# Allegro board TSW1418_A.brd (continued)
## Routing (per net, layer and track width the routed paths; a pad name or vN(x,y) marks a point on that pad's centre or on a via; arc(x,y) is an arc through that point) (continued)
HA22_N: length 53.2
  TOP w0.152: U9.G4 v1(42.44,40.12)
  LY3-SIGNAL w0.127: v2(6.48,33.48) 6.95,33.95 18.22,33.95 19.13,34.85 19.64,34.85 20.05,34.43 20.05,33.66 20.37,33.34 20.83,33.34 21.15,33.66 21.15,34.43 21.27,34.56 21.45,34.56 21.58,34.43 21.58,33.66 21.9,33.34 22.35,33.34 22.67,33.66 22.67,34.43 22.8,34.56 22.98,34.56 23.1,34.43 23.1,33.66 23.42,33.34 23.87,33.34 24.19,33.66 24.19,34.43 24.32,34.56 24.5,34.56 24.63,34.43 24.63,34.27 24.95,33.95 26.44,33.95 27.2,34.71 27.2,35.43 27.33,35.56 27.86,35.56 28.18,35.88 28.18,36.63 28.31,36.75 28.49,36.75 28.62,36.63 28.62,34.69 28.94,34.37 29.39,34.37 29.71,34.69 29.71,36.63 29.83,36.75 30.01,36.75 30.14,36.63 30.14,35.88 30.46,35.56 31.05,35.56 31.81,36.32 38.86,36.32 39.82,37.28 40.99,37.28 41.78,38.07 42.04,38.33 42.04,39.5 42.44,39.9 v1(42.44,40.12)
HA22_P: length 53.2
  TOP w0.152: U9.G3 v1(41.64,40.12)
  LY3-SIGNAL w0.127: v1(41.64,40.12) 41.64,39.87 41.28,39.5 41.28,38.09 40.8,37.61 39.69,37.61 38.73,36.65 37.77,36.65 37.6,36.83 37.34,36.83 37.16,36.65 36.91,36.65 36.73,36.83 36.48,36.83 36.3,36.65 36.05,36.65 35.87,36.83 35.62,36.83 35.44,36.65 35.18,36.65 35.01,36.83 34.75,36.83 34.57,36.65 33.63,36.65 33.42,36.87 33.24,36.87 33.02,36.65 31.67,36.65 30.91,35.89 30.6,35.89 30.47,36.02 30.47,36.76 30.15,37.08 29.7,37.08 29.38,36.76 29.38,34.82 29.25,34.7 29.07,34.7 28.95,34.82 28.95,36.76 28.63,37.08 28.17,37.08 27.85,36.76 27.85,36.02 27.73,35.89 27.19,35.89 26.87,35.57 26.87,34.85 26.3,34.28 25.08,34.28 24.96,34.4 24.96,34.57 24.64,34.89 24.18,34.89 23.86,34.57 23.86,33.79 23.74,33.67 23.56,33.67 23.43,33.79 23.43,34.57 23.11,34.89 22.66,34.89 22.34,34.57 22.34,33.79 22.21,33.67 22.04,33.67 21.91,33.79 21.91,34.57 21.59,34.89 21.14,34.89 20.82,34.57 20.82,33.79 20.69,33.67 20.51,33.67 20.38,33.79 20.38,34.57 19.77,35.18 18.99,35.18 18.09,34.28 6.95,34.28 v2(6.48,34.75)
HA23_N: length 53.2
  TOP w0.152: U9.G6 v1(44.04,40.12)
  LY3-SIGNAL w0.127: v2(5.21,32.21) 5.68,32.68 29.02,32.68 29.49,33.15 30.74,33.15 31.25,33.65 31.25,33.91 31.38,34.04 31.56,34.04 31.68,33.91 31.68,33.09 32,32.77 32.45,32.77 32.77,33.09 32.77,33.91 32.9,34.04 33.08,34.04 33.21,33.91 33.21,33.09 33.53,32.77 33.98,32.77 34.3,33.09 34.3,33.91 34.42,34.04 34.6,34.04 34.73,33.91 34.73,33.09 35.05,32.77 35.5,32.77 35.82,33.09 35.82,33.91 35.95,34.04 36.13,34.04 36.25,33.91 36.25,33.09 36.57,32.77 37.03,32.77 37.35,33.09 37.35,33.63 37.47,33.76 39.56,33.76 41.54,35.74 43.06,35.74 43.55,36.23 43.55,37.27 43.55,38.65 43.86,38.95 44.19,38.95 44.41,39.17 44.41,39.75 v1(44.04,40.12)
HA23_P: length 53.2
  TOP w0.152: U9.F6 v1(44.04,40.92)
  LY3-SIGNAL w0.127: v1(44.04,40.92) 43.61,40.48 43.61,39.17 43.22,38.78 43.22,38.37 43.08,38.22 43.08,37.94 43.22,37.79 43.22,37.16 43.22,36.37 42.93,36.07 41.4,36.07 39.42,34.09 37.34,34.09 37.02,33.77 37.02,33.22 36.89,33.1 36.71,33.1 36.58,33.22 36.58,34.05 36.26,34.37 35.81,34.37 35.49,34.05 35.49,33.22 35.37,33.1 35.19,33.1 35.06,33.22 35.06,34.05 34.74,34.37 34.29,34.37 33.97,34.05 33.97,33.22 33.84,33.1 33.66,33.1 33.54,33.22 33.54,34.05 33.22,34.37 32.76,34.37 32.44,34.05 32.44,33.22 32.32,33.1 32.14,33.1 32.01,33.22 32.01,34.05 31.69,34.37 31.24,34.37 30.92,34.05 30.92,33.79 30.61,33.48 29.35,33.48 28.88,33.01 5.68,33.01 v2(5.21,33.48)
INIT_B_0: length 78.4
  TOP w0.127: R21.2 v1(44.96,28.19)
  TOP w0.152: U9.P7 v1(44.84,33.72) ; v1(107.82,26.16) 107.82,22.1 107.52,21.79 U20.2
  LY3-SIGNAL w0.127: v1(44.96,28.19) 44.96,27.18 45.59,26.54 45.59,25.53 45.85,25.27 49.52,25.27 49.63,25.38 49.94,25.38 50.05,25.27 52.86,25.27 53.36,25.77 90.34,25.77 90.34,25.83 90.55,26.05 90.86,26.05 91.07,25.83 91.07,25.77 91.19,25.77 91.58,26.16 v1(107.82,26.16)
  LY5-SIGNAL w0.127: v1(44.96,28.19) 44.96,28.7 45.34,29.08 45.34,32.38 44.84,32.88 v1(44.84,33.72)
JTAG_BS_EN: length 9.9
  TOP w0.152: U7.15 91.38,29.72 R19.1 84.71,29.72 R92.2
JTAG_SEL: length 49.7
  TOP w0.127: U20.5 v1(109.65,20.49) ; v1(95.77,29.09) U7.1 98.8,29.09 R18.1
  LY5-SIGNAL w0.127: v1(95.77,29.09) 95.77,29.07 97.41,27.43 102.74,27.43 106.68,23.5 106.68,23.46 v1(109.65,20.49)
  BOTTOM w0.254: v1(109.65,20.49) 103.63,14.48 88.65,14.48 87.5,13.34 TP9.1
LED0: length 43
  TOP w0.152: R88.2 68.81,24.92 66.88,22.99 v1(66.8,22.99) U18.1 ; U9.B12 v1(49.64,44.12)
  BOTTOM w0.152: v1(49.64,44.12) 50.98,44.12 51.44,44.58 53.06,44.58 53.09,44.55 53.4,44.55 53.43,44.58 59.05,44.58 60.5,43.13 60.5,42.16 60.45,42.11 60.45,38.79 69.15,30.09 69.15,24.07 68.07,22.99 v1(66.8,22.99)
LED1: length 44
  TOP w0.127: U18.3 v1(67.31,20.45) ; 67.94,26.15 v1(67.94,24.89)
  TOP w0.152: U9.B11 48.55,43.72 v1(48.9,44.07) ; R87.2 67.03,27.06 67.94,26.15
  LY3-SIGNAL w0.127: v1(67.94,24.89) 67.94,22.48 67.31,21.84 v1(67.31,20.45)
  BOTTOM w0.152: v1(67.94,24.89) 67.94,26.67 60.33,34.29 60.33,38.48 59.69,39.12 59.69,41.78 60.2,42.29 60.2,42.93 59.44,43.69 52.7,43.69 52.32,43.31 52.07,43.31 51.68,43.7 51.09,43.7 51.08,43.69 49.28,43.69 v1(48.9,44.07)
LED2: length 48
  TOP w0.127: U18.5 v1(67.18,17.91) ; R89.2 61.25,31.72 62.78,30.19 62.78,26.84 65.05,24.56 66.98,24.56 v1(67.18,24.77) ; U9.F15 v1(52.04,40.92)
  LY3-SIGNAL w0.127: v1(67.18,24.77) 67.18,22.11 66.94,21.87 66.94,20.3 67.18,20.06 v1(67.18,17.91)
  BOTTOM w0.152: v1(52.04,40.92) 53.11,40.92 53.53,40.5 53.8,40.5 53.91,40.39 54.36,40.39 54.48,40.26 56.01,40.26 56.87,39.4 56.87,36.88 57.78,35.97 57.78,33.43 57.94,33.27 60.2,33.27 63.88,29.59 63.88,26.29 65.15,25.02 66.93,25.02 v1(67.18,24.77)
LED3: length 46.8
  TOP w0.127: U18.9 67.82,16.64 67.18,16 55.5,16 54.61,16.89 v1(54.61,20.65) ; U9.H14 v1(51.24,39.32)
  LY5-SIGNAL w0.127: v1(51.24,39.32) 51.13,39.32 50.7,38.88 50.29,38.88 50.04,38.63 50.04,37.97 50.55,37.47 55.5,37.47 56.52,36.45 56.52,32.51 57.28,31.75 57.28,28.71 57.17,28.6 57.17,28.3 57.28,28.19 57.28,23.24 54.69,20.65 v1(54.61,20.65)
MISO: length 75.6
  TOP w0.127: U9.J14 v1(51.24,38.52)
  TOP w0.152: U7.6 v1(95.72,32.34)
  LY5-SIGNAL w0.127: 94.87,31.5 94.49,31.88 89.55,31.88 88.42,30.75 77.46,30.75 74.8,33.4 71.37,33.4 69.47,35.31 63.63,35.31 60.7,38.24 55.38,38.24 55.17,38.02 52.02,38.02 51.52,38.52 v1(51.24,38.52)
  LY5-SIGNAL w0.152: v1(95.72,32.34) 94.87,31.5 94.87,27.18 95.89,26.16 101.73,26.16 102.23,25.65 J11.3
MOSI: length 60.6
  TOP w0.127: U7.10 v1(93.7,32.99) ; v1(103.25,32) U10.2
  TOP w0.152: U9.G17 v1(53.64,40.12)
  LY3-SIGNAL w0.127: v1(93.7,32.99) 96.55,32.99 98.17,31.37 99.31,31.37 100.46,32.51 102.74,32.51 v1(103.25,32)
  LY5-SIGNAL w0.127: v1(93.7,32.99) 93.42,33.27 89.66,33.27 87.69,31.31 79.82,31.31 76.71,34.42 74.42,34.42 71.88,36.96 66.04,36.96 65.53,37.47 62.87,37.47 60.21,40.12 v1(53.64,40.12)
MOSI_Z: length 31.8
  TOP w0.152: U10.4 v1(108.16,29.8)
  LY5-SIGNAL w0.152: v1(108.16,29.8) 108.58,29.37 108.58,25.53 108.2,25.15 108.2,23.37 110.49,21.08 110.49,11.96 110.34,11.81 100.97,11.81 J11.5
OSC-OUT: length 23.8
  TOP w0.152: R38.2 v1(64.64,48.13) ; U9.H16 v1(52.84,39.32)
  LY3-SIGNAL w0.127: v1(64.64,48.13) 54.36,48.13 50.04,43.81 50.04,42.67 50.42,42.29 50.43,42.29 50.81,41.91 50.81,40.84 52.3,39.34 52.82,39.34 v1(52.84,39.32)
PROGRAM_B_0: length 70
  TOP w0.127: v1(106.63,28.91) R86.2 U20.1 ; U9.P9 v1(46.44,33.72)
  LY3-SIGNAL w0.127: v1(46.44,33.72) 46.93,33.72 47.37,33.27 49.48,33.27 49.49,33.28 61.8,33.28 62.57,32.51 67.44,32.51 71.37,28.57 86.36,28.57 87.25,29.46 97.03,29.46 97.54,28.96 105.66,28.96 105.71,28.91 v1(106.63,28.91)
SCL: length 175
  TOP w0.127: U14.5 133.46,11.13 132.92,11.67 131.46,11.67 ; 121.17,13.46 121.17,13.57 121.03,13.72 120.65,13.72 120.14,14.22 112.65,14.22 112.39,14.48 112.39,21.14 U20.6 ; 121.17,13.46 U17.1 ; 121.17,13.46 v1(121.67,13.96) U17.2 ; U16.5 133.46,36.72 133.1,37.08 131.7,37.08 131.46,36.85 ; U9.F18 v1(63.04,40.52) ; 131.46,11.67 130.86,12.27 U17.5 v1(123.17,13.95) ; 131.46,11.67 U14.1 ; 123.17,37.35 122.68,37.85 121.41,37.85 121.17,37.61 U12.1 ; 123.17,37.35 U12.5 123.17,34.69 123.44,34.42 123.95,34.42 v1(124.21,34.67) ; 123.17,37.35 130.95,37.35 131.46,36.85 ; 131.46,36.85 U16.1 ; U4.44 v1(95.98,36.1)
  TOP w0.152: R97.2 121.15,35.66 U12.1
  LY5-SIGNAL w0.127: v1(124.21,34.67) 124.21,33.27 123.44,32.51 123.44,24.89 124.33,24 124.33,20.57 126.05,18.86 126.05,14.41 125.73,14.1 123.32,14.1 v1(123.17,13.95) 123.17,13.96 v1(121.67,13.96) 116.71,18.92 113.67,18.92 112.39,20.19 112.39,28.07 108.33,32.13 108.33,34.54 106.05,36.83 96.65,36.83 95.98,36.17 v1(95.98,36.1) 95.4,35.51 78.61,35.51 74.88,39.24 73.03,39.24 72.26,38.48 70.25,38.48 69.61,39.12 63.75,39.12 63.04,39.83 v1(63.04,40.52)
SCLK: length 76.4
  TOP w0.127: v1(50.44,38.52) U9.J13
  TOP w0.152: U7.13 v1(92.78,31.04)
  LY5-SIGNAL w0.127: v1(92.78,31.04) 92.58,31.24 89.31,31.24 86.83,28.77 77.91,28.77 74.17,32.51 70.87,32.51 68.58,34.8 63.63,34.8 60.47,37.96 55.86,37.96 55.65,37.74 51.03,37.74 50.44,38.33 v1(50.44,38.52)
  LY5-SIGNAL w0.152: v1(92.78,31.04) 90.82,29.08 89.79,29.08 88.01,27.3 88.01,18.16 93.09,13.08 J11.7
SDA: length 140.1
  TOP w0.127: 122.49,14.41 122.68,14.22 122.68,12.28 U17.4 122.67,10.3 124.59,8.38 132.46,8.38 132.96,8.88 U14.4 ; v1(113.34,21.79) U20.7 ; R85.1 97.03,36.32 v1(96.98,36.37) U4.46 ; v1(122.56,37.08) 122.67,36.97 U12.4 ; v1(108.12,36.37) 108.12,35.54 U8.4 ; U16.4 132.84,35.51 132.84,36.42 132.69,36.58 v1(132.11,36.58) 131.96,36.42 U16.2 ; U9.G18 54.2,39.72 54.48,40 55.71,40 55.99,39.72 v1(62.61,39.72)
  TOP w0.152: v1(113.34,21.79) 113.34,15.06 113.67,14.73 122.17,14.73 122.49,14.41
  LY3-SIGNAL w0.127: v1(96.98,36.37) 97.27,36.08 107.84,36.08 v1(108.12,36.37)
  LY5-SIGNAL w0.127: v1(122.56,37.08) 122.75,36.89 ; 122.75,36.89 123.06,36.58 v1(132.11,36.58) ; 122.75,36.89 122.22,36.37 114.2,36.37 113.34,35.5 113.34,34.9 113.18,34.75 ; v1(96.98,36.37) 95.42,34.8 78.61,34.8 74.8,38.61 73.66,38.61 73.03,37.97 70.36,37.97 69.85,38.48 62.99,38.48 62.61,38.86 v1(62.61,39.72) ; 113.18,34.75 113.06,34.62 110.31,34.62 108.57,36.37 v1(108.12,36.37) ; 113.18,34.75 113.18,21.95 v1(113.34,21.79)
SDA_OUT: length 13.8
  TOP w0.152: U4.45 v1(96.48,39.33) ; v1(105.46,38.69) U8.1 105.39,37.47 R96.2
  LY5-SIGNAL w0.127: v1(96.48,39.33) 97.13,38.69 v1(105.46,38.69)
SEN: length 77
  TOP w0.152: U9.H17 v1(53.64,39.32) ; U7.3 v1(95.8,30.39)
  LY5-SIGNAL w0.127: v1(95.8,30.39) 96.9,31.5 96.9,32.26 96.45,32.71 95.57,32.71 95.37,32.51 93.48,32.51 93.28,32.71 89.99,32.71 88.3,31.03 78.45,31.03 75.56,33.91 72.52,33.91 70.48,35.94 63.75,35.94 60.07,39.62 57.66,39.62 57.29,39.26 55.4,39.26 55.34,39.32 v1(53.64,39.32)
  LY5-SIGNAL w0.152: J11.1 104.78,24.38 102.23,26.92 96.52,26.92 95.25,28.19 95.25,29.82 95.8,30.37 v1(95.8,30.39)
SOUT0: length 3.4
  BOTTOM w0.279: R45.1 R99.2 C90.1 R46.2
SOUT1: length 3.4
  BOTTOM w0.279: R44.2 C89.1 R98.2 R43.1
SPI_D_Z: length 59.5
  TOP w0.127: U10.1 105.39,33.02 v1(103.38,33.02) ; U4.43 95.48,36.56 v1(95.25,36.32)
  TOP w0.152: U9.J15 51.67,38.12 52.05,37.74 54.2,37.74 54.21,37.74 55.24,37.74 55.93,37.06 62.36,37.06 64.59,34.82 77.32,34.82 78.49,35.99 v1(91.67,35.99)
  LY3-SIGNAL w0.127: v1(95.25,36.32) 95.25,35.05 95.76,34.54 101.85,34.54 v1(103.38,33.02)
  BOTTOM w0.152: v1(91.67,35.99) 94.92,35.99 v1(95.25,36.32)
SYNC0: length 4.4
  TOP w0.279: U9.A10 47.75,44.63 v1(47.75,48.9)
SYNC0_VADJ: length 25.8
  TOP w0.254: U9.R3 v1(41.64,32.92)
  LY3-SIGNAL w0.127: v1(48.77,52.2) 49.4,51.56 49.4,48.78 46.88,46.25 46.88,44.81 46.99,44.7 46.99,35.18 46.74,34.92 42.67,34.92 41.64,33.9 v1(41.64,32.92)
SYNC1: length 5
  TOP w0.279: U9.A11 48.44,46.67 50.04,48.26 v1(50.04,48.9)
SYNC1_VADJ: length 25.1
  TOP w0.152: U9.P4 v1(42.44,33.72)
  LY3-SIGNAL w0.127: v1(51.05,52.2) 50.67,51.82 50.67,48.13 48.51,45.97 48.51,45.21 47.5,44.2 47.5,34.54 47.11,34.15 42.92,34.15 42.48,33.72 v1(42.44,33.72)
SYNC-OUT-0: length 19.9
  BOTTOM w0.279: R45.2 47.75,56.39 50.42,59.05 55.88,59.05 58.29,61.47 J8.1
SYNC-OUT-1: length 31.5
  BOTTOM w0.279: J7.1 71.63,59.31 69.47,57.15 52.07,57.15 50.04,55.12 R43.2
TCK: length 63.6
  TOP w0.127: J3.6 92.62,25.18 R79.2 94.11,26.67 94.11,29.59 93.3,30.39 U7.14 v1(89.83,30.39) ; U9.E10 47.64,41.32 v1(48.04,41.72)
  LY3-SIGNAL w0.127: v1(48.04,41.72) 48.07,41.72 48.48,41.31 48.48,38.99 48.53,38.94 49.74,38.94 50.08,38.6 50.08,38.19 50.16,38.1 50.75,38.1 50.81,38.04 50.98,37.87 51.38,37.87 51.66,37.6 51.81,37.6 51.97,37.44 52.05,37.44 52.08,37.41 52.31,37.41 52.56,37.41 52.64,37.34 56.11,37.34 56.23,37.21 61.08,37.21 62.67,35.62 62.67,35.36 63.11,34.92 89.11,34.92 89.26,35.07 89.56,35.07 89.77,34.86 89.77,34.81 90.08,34.5 90.08,30.65 v1(89.83,30.39)
TDI: length 62.8
  TOP w0.127: J3.10 96.61,24.67 94.74,26.54 94.74,30.73 v1(93.13,32.34) U7.11 ; v1(48.84,41.72) 48.44,41.32 U9.E11
  LY3-SIGNAL w0.127: v1(93.13,32.34) 92.94,32.34 92.45,32.84 92.45,33.03 90.04,35.43 63.88,35.43 61.85,37.47 61.53,37.47 61.03,37.97 56.23,37.97 56.01,37.75 52.62,37.75 52.57,37.69 52.19,37.69 52.01,37.87 51.78,37.87 51.5,38.15 51.09,38.15 50.81,38.44 50.81,38.67 50.6,38.88 50.27,38.88 50.04,39.12 50.04,39.44 49.8,39.68 49.47,39.68 49.28,39.88 49.28,41.27 48.84,41.71 v1(48.84,41.72)
TDO: length 75.3
  TOP w0.127: U9.E13 50.04,41.32 v1(50.44,41.72) ; U7.5 97.24,31.88 v1(98.42,31.88) ; J3.8 v1(94.61,25.02) ; v1(101.47,25.02) v1(101.47,31.88)
  LY3-SIGNAL w0.127: v1(98.42,31.88) 98.81,32.26 98.81,33.78 98.42,34.16 93.09,34.16 91.63,35.63 91.52,35.63 91.3,35.84 91.3,35.95 91.26,35.99 64.21,35.99 61.62,38.58 55.98,38.58 55.88,38.48 54.1,38.48 53.7,38.88 52.69,38.88 52.67,38.86 52.26,38.86 51.09,40.03 51.09,40.1 50.44,40.74 v1(50.44,41.72)
  LY5-SIGNAL w0.127: v1(101.47,31.88) v1(98.42,31.88) ; v1(94.61,25.02) v1(101.47,25.02)
TMS: length 77
  TOP w0.127: v1(49.64,41.72) 49.24,41.32 U9.E12 ; U7.2 v1(98.45,29.74) 98.81,30.1 R80.2 ; v1(100.74,29.74) v1(100.74,25.68) ; v1(90.7,25.68) 90.62,25.59 J3.4
  LY3-SIGNAL w0.127: v1(98.45,29.74) 96.95,31.24 95.25,31.24 93.86,32.63 93.85,32.63 93.55,32.63 93.33,32.84 93.33,33.15 93.34,33.15 90.78,35.71 64.1,35.71 61.71,38.1 61.59,38.1 61.42,38.27 56.11,38.27 55.93,38.1 52.66,38.1 52.64,38.07 52.21,38.07 52.13,38.15 51.89,38.15 51.68,38.37 51.68,38.6 51.33,38.95 51.09,38.95 50.88,39.17 50.88,39.4 50.6,39.68 50.35,39.68 50.04,40 50.04,41.33 v1(49.64,41.72)
  LY5-SIGNAL w0.127: v1(98.45,29.74) v1(100.74,29.74) ; v1(100.74,25.68) v1(90.7,25.68)
TRIG: length 6.8
  TOP w0.127: U9.A9 46.84,47.26 46.1,48.01 R39.2
  TOP w0.279: C85.2 R40.1 R39.2
TRIG-IN: length 17.4
  TOP w0.279: J5.1 44.96,60.96 43.81,59.82 C85.1
USB_EECLK: length 8.4
  TOP w0.152: U4.62 101.84,46.18 104.42,48.77 104.65,48.77 R8.2 U5.2
USB_EECS: length 10
  TOP w0.152: U5.1 R7.2 103.63,50.67 103.1,50.14 103.1,47.93 101.85,46.68 U4.63
USB_REF: length 1.8
  TOP w0.152: U4.6 v1(95.48,47.77)
  BOTTOM w0.152: R5.2 95.48,47.26 v1(95.48,47.77)
USB_RST: length 3.7
  TOP w0.381: U4.14 91.48,50.88 C18.1 R4.2
VADJ: length 37.6
  TOP w0.254: U9.D6 44.44,42.12 v1(44.04,42.52) ; U9.V8 46.04,30.68 v1(45.85,30.48) ; U9.N3 v1(41.64,34.52) ; U9.F2 v1(40.84,40.92) ; U9.L15 v1(52.04,36.12) ; v1(43.31,31.37) 43.31,31.38 U9.U5 ; U9.L17 v1(53.64,36.12) ; U9.J1 v1(40.15,38.12) ; U9.G5 v1(43.24,40.12) ; U9.P16 v1(52.84,33.72) ; U9.V18 v1(54.04,30.41) ; U9.P6 v1(44.04,33.72) ; U9.N13 v1(50.44,34.52) ; U9.T2 v1(40.84,32.12) ; U9.C3 v1(41.64,43.32) ; U9.A7 v1(45.24,44.93) ; U9.T12 v1(49.64,32.12) ; U9.K4 v1(42.44,36.92) ; U9.U15 v1(52.04,31.32)
  TOP w0.457: J13.2 116.16,19.48 ; J13.2 116.38,20.19 ; J13.2 114.5,20.19 ; J13.2 116.16,20.91 ; J13.2 115.44,21.13 ; J13.2 115.44,19.25 ; J13.2 114.73,20.91 ; J13.2 114.73,19.48
  TOP w0.508: C127.1 v1(118.62,20.19)
  LYR9-PWR w0.457: J13.2 115.44,21.13 ; J13.2 116.16,19.48 ; J13.2 116.16,20.91 ; J13.2 115.44,19.25 ; J13.2 116.38,20.19 ; J13.2 114.73,20.91 ; J13.2 114.5,20.19 ; J13.2 114.73,19.48
  BOTTOM w0.254: C50.1 41.62,34.54 v1(41.64,34.52) ; C52.1 39.69,38.12 v1(40.15,38.12) ; C57.1 51.92,35.99 v1(52.04,36.12) ; v1(45.85,30.48) 45.85,29.9 C53.1 ; C56.1 52.83,33.71 v1(52.84,33.72) ; C43.1 v1(52.5,30.4) ; v1(40.84,40.92) 40.79,40.92 40.73,40.97 40.26,41.45 39.7,41.45 39.45,41.2 39.45,41.18 C47.1 ; v1(42.44,36.92) 42.36,36.83 C58.1 ; C40.1 v1(42.55,46.1) ; C59.1 v1(55.19,32.82) ; v1(45.24,44.93) 45.24,45.45 C51.1 ; C45.1 v1(43.31,31.37)
  BOTTOM w0.508: C54.1 v1(55.37,29.97) ; C54.1 v1(56.26,30.1) ; C54.1 v1(56.39,30.99)
  vias: v1(39.29,43.15) v1(39.42,39.12) v1(39.55,42.16) v1(42.34,47.62) v2(7.75,10.62) v2(9.02,11.89) v2(10.29,10.62) v2(11.56,11.89)
N24747082: length 2.9
  TOP w0.152: U5.4 105.54,46.86 R10.2 R9.2
N25673570: length 6.9
  TOP w0.254: U4.9 v1(93.98,47.25)
  BOTTOM w0.254: v1(93.98,47.25) 93.98,49.13 C2.1 C1.1 FB1.1
N25674940: length 6.8
  TOP w0.254: v1(96.39,47.37) 96.48,47.46 U4.4
  BOTTOM w0.254: v1(96.39,47.37) 96.62,47.6 C12.1 C14.1 FB2.1
N27319544: length 11
  TOP w0.152: 101.68,53.05 C19.1 ; 101.68,53.05 101.68,52.66 101.17,52.15 100.99,52.15 100.92,52.22 100.73,52.22 100.6,52.08 100.6,51.89 100.66,51.83 100.66,51.64 100.46,51.44 100.07,51.44 99.82,51.18 99.61,51.18 99.49,51.31 99.49,51.56 99.36,51.69 99.16,51.69 99.03,51.56 99.03,51.31 98.9,51.18 98.7,51.18 98.57,51.31 98.57,51.56 98.45,51.69 98.24,51.69 97.99,51.44 97.66,51.44 97.48,51.26 U4.2 ; 101.68,53.05 Y1.1
N27322325: length 11.1
  TOP w0.152: Y1.3 101.66,56.24 C21.1 96.98,53.17 U4.3
N29832220: length 0.8
  TOP w0.254: FB4.1 v1(90.68,60.45)
  vias: v1(88.52,69.98) v1(88.52,67.82) v1(88.52,63.63) v1(88.52,61.59) v1(89.03,67.18) v1(89.03,64.77) v1(89.03,60.96) v1(89.03,59.94) v1(89.66,61.59) v1(89.92,65.91) v1(90.68,67.18) v1(90.68,64.77) v1(91.19,69.72) v1(91.19,67.82) v1(91.31,64.26) v1(91.31,61.72) v1(91.57,63.12) v1(92.96,69.85) v1(92.96,68.2) v1(94.36,69.09) v1(94.36,67.18) v1(94.36,65.15) v1(95.76,69.85) v1(95.76,68.2) v1(97.41,69.72) v1(97.41,67.82) v1(97.41,64.01) v1(97.41,62.1) v1(98.04,64.64) v1(98.17,67.18) v1(98.68,65.79) v1(99.31,67.18) v1(99.44,64.64) v1(99.95,61.59) v1(100.08,69.98) v1(100.08,66.04)
N46253696: length 3.7
  TOP w0.152: J2.1 95.94,60.65 C16.1 FB3.1
N46253708: length 12.5
  TOP w0.152: R3.1 FB3.2 98.3,58.17 102.11,61.98 102.11,63.25 TP7.1
N46266315: length 1.7
  TOP w0.254: C15.1 111.72,40.2 U2.4
N46266800: length 3.4
  TOP w0.254: U4.59 101.71,44.68 101.98,44.96 101.98,43.81
N46270507: length 7.2
  TOP w0.152: U9.P11 v1(48.84,33.72) ; v1(48.64,28.32) 49.15,28.07 R22.2
  LY5-SIGNAL w0.127: v1(48.84,33.72) 48.77,33.64 48.77,31.85 48.48,31.56 48.48,29.56 48.39,29.46 48.39,28.57 v1(48.64,28.32)
N46270525: length 7
  TOP w0.152: v1(51.44,28.45) R23.2 ; U9.P13 v1(50.44,33.72)
  LY5-SIGNAL w0.127: v1(51.44,28.45) 51.44,28.96 51.24,29.15 51.24,29.23 51.03,29.44 51.03,29.63 51.02,29.64 51.02,29.73 50.93,29.82 50.93,31.12 50.88,31.17 50.88,31.47 50.93,31.52 50.93,32.72 50.88,32.77 50.88,33.07 50.44,33.5 v1(50.44,33.72)
N46270552: length 7.8
  TOP w0.152: v1(50.55,28.32) 50.29,28.07 R24.2 ; U9.P12 v1(49.64,33.72)
  LY5-SIGNAL w0.127: v1(49.64,33.72) 49.64,33.41 49.52,33.28 49.49,33.28 49.28,33.07 49.28,32.9 49.28,32.89 49.28,28.96 49.91,28.32 v1(50.55,28.32)
N46270638: length 7.3
  TOP w0.127: R25.2 v1(46.1,28.19)
  TOP w0.152: U9.P8 v1(45.64,33.72)
  LY5-SIGNAL w0.127: v1(46.1,28.19) 46.1,28.7 45.64,29.16 45.64,29.76 46.21,30.33 46.21,30.63 45.64,31.2 v1(45.64,33.72)
N46271778: length 2
  TOP w0.152: R1.2 86.66,40.68 U4.30
N46271783: length 2.1
  TOP w0.254: U4.55 101.97,42.68 101.98,42.67
N46280543: length 3.5
  TOP w0.152: R13.2 67.06,37.95 C23.1 67.46,38.35 U6.2
N46280553: length 3.5
  TOP w0.152: U6.1 67.57,39 C22.1 67.06,39.52 R12.2
N46323629: length 2.2
  TOP w0.152: R33.2 TP11.1
N46323688: length 2.2
  TOP w0.152: R34.2 TP12.1
N46333997: length 3.8
  TOP w0.254: C92.1 R49.2 121.07,51.5 U11.1
N46334199: length 44.6
  TOP w0.127: v1(130.63,25.7) 131.23,25.7 131.36,25.83 U13.1 ; v1(117.6,51.82) R50.1
  LY5-SIGNAL w0.127: v1(130.63,25.7) 130.63,27.26 131.83,28.45 131.83,30.48 133.6,32.26 133.6,35.18 133.35,35.43 133.35,36.96 130.78,39.53 130.78,43.08 128.78,45.09 128.78,50.67 127.51,51.94 117.73,51.94 v1(117.6,51.82)
  BOTTOM w0.127: R77.2 119.13,50.29 v1(117.6,51.82)
N46334233: length 5.8
  TOP w0.254: U11.7 121.72,55.05 122.43,55.75 122.43,57.18 R52.1 R51.2
N46334693: length 5.3
  TOP w0.254: 122.17,41.4 121.67,40.9 U12.9 ; 122.17,41.4 122.17,41.76 C96.2 122.45,43.64 R54.2 ; 122.17,41.4 U12.8
N46334712: length 3.8
  TOP w0.254: R53.2 120.9,42.06 C96.1 121.17,41.74 U12.10
N46335690: length 5.9
  TOP w0.254: U13.7 132.01,29.39 132.28,29.67 132.48,29.67 132.64,29.83 132.64,30.02 132.72,30.1 132.72,31.14 R64.2 R58.1
N46335801: length 5.4
  TOP w0.254: U14.9 131.96,14.99 132.46,15.49 ; 132.46,15.49 132.46,15.72 C103.2 132.72,16.03 R60.2 ; 132.46,15.49 U14.8
N46335828: length 3.8
  TOP w0.254: U14.10 131.46,15.71 C103.1 131.17,17.6 R59.2
N46336358: length 1.9
  TOP w0.254: R62.1 131.72,50.44 131.95,50.67 131.95,51.43 132.01,51.48 U15.2
N46336380: length 5.7
  TOP w0.152: 132.01,54.43 132.01,55.05 132.59,55.63 132.59,57.05 R63.2 R57.1
  TOP w0.254: U15.7 132.01,54.43
N46336491: length 5.7
  TOP w0.254: R66.2 132.72,41.81 C109.2 132.46,41.5 ; 132.46,41.5 131.96,41 U16.9 ; 132.46,41.5 U16.8
N46336518: length 3.8
  TOP w0.254: U16.10 131.46,41.49 C109.1 131.17,43.38 R65.2
N46342790: length 5.4
  TOP w0.279: R72.2 122.45,20.27 C119.2 122.17,18.39 122.17,17.78 ; U17.9 121.67,17.77 121.68,17.78 122.17,17.78 ; 122.17,17.78 U17.8
N46342817: length 3.8
  TOP w0.279: U17.10 121.17,18.37 C119.1 120.88,20.27 R71.2
N46365358: length 1.7
  TOP w0.279: U1.4 122.62,31.92 C123.1
N46372732: length 2.5
  TOP w0.254: R37.2 70.35,52.71 Y2.1
N46372902: length 1.8
  TOP w0.254: Y2.3 R38.1
N46384300: length 1.2
  TOP w0.127: D3.2 R81.1
N46384467: length 1.2
  TOP w0.127: D4.2 R6.1
N46384557: length 1.2
  TOP w0.127: D5.2 R82.1
N46384754: length 1.2
  TOP w0.127: D6.2 R83.1
N46384902: length 1.2
  TOP w0.127: D7.2 R84.1
N46387156: length 1.9
  TOP w0.254: D2.1 R26.2
N46388372: length 9.5
  TOP w0.127: R6.2 61.34,27.18 62.23,26.29 62.23,22.1 62.61,21.72 U18.2
N46388377: length 7.2
  TOP w0.127: U18.4 62.87,19.18 61.34,20.7 61.34,22.35 60.96,22.73 R81.2
N46388382: length 5.5
  TOP w0.127: U18.6 62.61,16.64 60.96,18.29 R82.2
N46388387: length 13.2
  TOP w0.127: R83.2 65.66,9.4 69.85,13.59 69.85,15.34 U18.8
N46388402: length 15.4
  TOP w0.127: U18.10 71.12,17.91 71.63,17.4 71.63,16.51 71.12,16 68.33,16 67.44,15.11 66.93,15.11 65.66,13.84 R84.2
N46435188: length 19
  TOP w0.127: SW1.2 R15.1
  TOP w0.152: v1(48.04,43.32) 47.64,42.92 U9.C10
  LY5-SIGNAL w0.127: SW1.2 56.54,53.85 53.9,53.85 51.34,51.29 51.42,51.21 51.42,50.9 51.21,50.69 51.21,49.1 48.56,46.46 48.56,44.88 48.47,44.79 48.47,43.74 v1(48.04,43.32)
N46505112:
  vias: v2(10.29,60.15)
N46505156:
  vias: v2(12.83,60.15)
N46505187:
  vias: v2(7.75,60.15)
N463339328: length 1.9
  TOP w0.152: v1(121.72,51.12) U11.2
  BOTTOM w0.152: R77.1 121.72,50.58 v1(121.72,51.12)
N463356088: length 1.9
  TOP w0.152: v1(132.01,25.08) U13.2
  BOTTOM w0.152: R78.1 132.01,24.41 v1(132.01,25.08)

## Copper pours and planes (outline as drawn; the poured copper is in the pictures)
1.8V on TOP: 132.59,29.46 131.7,29.46 131.7,28.07 129.16,28.07 129.16,26.67 123.7,26.67 123.7,31.75 126.36,34.42 131.44,34.42 131.44,33.02 129.79,33.02 129.79,31.11 132.59,31.11
1.8V on BOTTOM: 113.92,18.92 113.92,14.86 117.09,14.86 117.09,18.92
1.8V on LY7-PWR: 117.35,25.53 122.05,30.23 122.05,30.48 123.06,31.5 123.06,35.05 52.7,35.05 52.7,29.97 51.44,28.7 50.42,28.7 49.28,29.84 49.28,38.86 47.5,38.86 47.5,39.75 49.28,39.75 49.28,41.27 50.04,41.27 50.04,41.4 121.54,41.4 121.54,39.42 121.79,39.17 128.5,39.17 128.52,39.14 128.52,34.72 132.21,34.72 132.46,34.47 132.46,30.18 131.67,29.39 131.67,28.17 128.55,28.17 128.52,28.19 128.52,26.42 123.06,26.42 123,26.35 121.6,26.35 120.27,25.02 120.27,22.73 119.38,21.84 119.38,14.86 112.78,14.86 112.78,18.92 117.22,18.92 117.35,19.05
1.8V_USB on LYR9-PWR: 90.55,49.66 90.55,37.47 101.85,37.47 101.85,49.66
1V on TOP: 122.17,54.23 117.86,54.23 117.86,54.61 116.08,54.61 116.08,62.81 117.53,64.26 121.51,64.26 122.2,63.58 122.2,61.39 121.03,60.22 121.03,57.28 122.17,57.28
1V on LY7-PWR: 44.58,34.16 44.58,41.53 45.34,41.53 45.34,53.21 44.7,53.21 44.7,57.15 105.28,57.15 110.49,62.36 116.2,62.36 116.2,65.15 122.94,65.15 122.94,58.29 123.32,57.91 123.32,55.5 121.92,55.5 121.92,55.09 121.41,54.58 121.4,54.6 116.07,54.6 115.95,54.48 115.95,50.04 47.62,50.04 47.62,41.53 49.15,41.53 49.15,40.13 48.26,40.13 48.26,39.88 47.37,39.88 47.37,38.48 49.15,38.48 49.15,29.46 49.78,28.83 49.78,28.07 47.5,28.07 47.24,28.32 47.24,33.4 46.48,34.16
2.5V on TOP: 121.54,29.34 116.84,29.34 116.84,21.59 113.92,21.59 113.92,22.23 113.41,22.73 113.41,32.89 121.54,32.89
2.5V on BOTTOM, LY7-PWR: 113.03,33.66 121.67,33.66 121.67,30.86 116.97,26.16 116.97,21.72 113.03,21.72
3.3V on TOP: 122.99,41.22 122.99,39.4 126.9,39.4 128.07,40.56 128.07,44.96 127.36,45.67 124.59,45.67 123.8,44.88 123.8,41.45 123.57,41.22
3.3V on TOP: 68.71,21.34 68.71,23.88 71.5,23.88 71.5,21.34
3.3V on TOP: 133.3,39.04 133.3,40.92 135.76,40.92 135.76,39.04
3.3V on TOP: 123.01,18.01 123.01,16.23 125.27,16.23 125.27,18.01
3.3V on TOP: 87.12,29.08 87.12,23.5 92.84,23.5 92.84,29.08
3.3V on TOP: 133.35,15.29 133.35,13.21 135.59,13.21 135.59,15.29
3.3V on TOP: 129.97,56.9 129.97,54.71 132.36,54.71 132.36,56.9
3.3V on LY7-PWR: 42.29,9.02 42.29,9.78 12.32,9.78 12.32,18.16 42.29,18.16 42.29,33.53 46.74,33.53 46.86,33.4 46.86,32.77 46.61,32.51 46.61,27.56 55.12,27.56 55.12,30.48 97.66,30.48 100.97,33.78 111.51,33.78 112.27,33.02 112.27,21.84 110.36,19.94 58.55,19.94 58.55,9.02
3.3V on LYR9-PWR: 136.78,70.36 136.78,8.26 137.03,8 137.03,0.89 15.11,0.89 14.48,1.52 14.48,7.24 1.14,7.24 1.14,70.1 1.4,70.36 ; 2 cut-outs
3.3V_USB on TOP: 109.19,42.24 109.19,43.51 110.44,43.51 110.44,42.24
3.3V_USB on LY3-SIGNAL: 64.52,35.69 64.52,41.15 70.36,41.15 70.36,41.27 87.63,41.27 87.63,53.85 113.16,53.85 113.16,36.7 113.67,36.2 119,36.2 119,34.8 111.76,34.8 111.76,36.83 75.44,36.83 75.44,35.69
3.3V_USB on LY7-PWR: 109.22,43.74 109.22,42.39 110.62,42.39 110.62,43.74
5V_EXT on LYR9-PWR: 113.54,43.43 113.54,53.72 108.71,53.72 108.71,61.59 124.71,61.59 124.71,69.85 129.92,69.85 129.92,61.59 130.05,61.59 130.05,60.2 128.14,58.29 128.14,53.72 119.38,53.72 119.38,43.43
5V_PWR on TOP, BOTTOM: 121.28,44.83 118.75,44.83 118.75,48.77 121.28,48.77
5V_PWR on TOP, BOTTOM: 121.41,21.34 119.63,21.34 119.63,25.53 121.41,25.53
5V_PWR on TOP, BOTTOM: 131.83,44.45 129.67,44.45 129.67,50.55 131.06,50.55 131.06,45.72 131.83,45.72
5V_PWR on TOP, BOTTOM: 129.41,18.67 129.41,25.15 131.06,25.15 131.06,19.68 131.83,19.68 131.83,18.67
5V_PWR on TOP, BOTTOM, LY5-SIGNAL: 122.56,69.72 122.56,59.69 132.46,59.69 132.46,69.72
5V_PWR on LY7-PWR: 120.02,18.8 120.02,20.57 119.76,20.83 119.76,21.84 120.78,22.86 120.78,24.89 120.9,25.02 120.9,25.15 121.28,25.53 132.84,25.53 132.84,35.69 130.3,35.69 130.3,44.2 118.77,44.2 118.75,44.22 118.75,44.96 118.77,44.98 118.77,50.39 116.46,52.7 116.46,54.43 118.24,54.43 118.26,54.46 118.29,54.46 118.8,53.95 124.71,53.95 124.71,62.48 123.19,62.48 123.19,65.02 122.56,65.66 122.3,65.66 122.3,69.72 132.97,69.72 132.97,66.8 136.65,63.12 136.65,48.39 137.54,47.5 137.54,18.8
5V_USB on LYR9-PWR: 101.98,41.27 101.98,55.75 99.19,55.75 99.19,69.85 122.81,69.85 122.81,63.88 105.66,63.88 105.66,43.94 107.19,42.42 108.71,42.42 108.71,39.88 106.3,39.88 104.9,41.27
GND on LY2-GND, LY4-GND, LYR8-GND: 138.05,70.74 138.05,0.38 0.38,0.38 0.38,70.74
GND on LY6-GND: 138.05,70.74 138.05,0.38 0.38,0.38 0.38,70.74
GND on LY7-PWR: 107.98,44.73 107.98,43.89 109.27,43.89 109.27,44.73
VADJ on TOP: 113.92,18.8 119.51,18.8 119.51,21.21 113.92,21.21
VADJ on LYR9-PWR: 37.97,4.19 37.97,8.51 15.24,8.51 15.24,16.51 12.19,16.51 12.19,10.16 12.45,9.91 12.45,8.51 6.86,8.51 6.86,19.81 20.83,19.81 23.24,17.4 37.97,17.4 37.97,32.13 32.38,32.13 29.97,34.54 3.68,34.54 3.68,58.29 4.57,59.18 36.7,59.18 40.89,54.99 40.89,49.53 41.91,48.51 48.77,48.51 48.77,47.37 46.99,45.59 46.99,45.31 46.89,45.31 46.89,44.6 46.99,44.6 46.99,42.8 48.77,42.8 48.77,42.16 51.94,38.99 50.29,37.34 50.29,36.58 50.93,35.94 51.18,35.94 51.94,36.7 53.47,36.7 53.85,37.08 55.75,37.08 57.02,35.81 57.02,29.84 54.61,27.43 54.61,8.26 57.15,8.26 57.53,8.64 57.53,21.84 118.62,21.84 118.75,21.72 118.75,9.53 113.41,4.19
N29832220 on TOP, LY7-PWR: 88.65,59.69 88.65,61.34 88.39,61.34 88.39,70.23 100.33,70.23 100.33,61.34 96.65,61.34 96.65,64.77 91.95,64.77 91.95,59.69

Small or netless copper shapes (teardrops, artwork), in the pictures only: 2 on TOP, 2 on LY7-PWR

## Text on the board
BOTTOM: LAYER 10 - BOTTOM
Board Geometry/Soldermask Bottom: SOLDERMASK BOTTOM
Ref Des/Silkscreen Bottom: SILKSCREEN BOTTOM
User.Comments: TSW1418EVM REV A | TEXAS INSTRUMENTS | 7.  SMOBC/IMMERSION GOLD: 2-55uIN OVER 118-236uIN NICKEL PLATING. | ALL OUTER LAYERS USING A 11MIL TRACE WIDTH SHALL BE 50 OHMS SINGLE ENDED+/- 10%. | 14. ALL INNER LAYERS USING A 5MIL TRACE WIDTH AND 8MIL SPACING SHALL BE 100 OHMS DIFFERENTIAL +/- 10%. | 18. ALL THROUGH VIAS TO BE PLUGGED WITH NON-CONDUCTIVE EPOXY MATERIAL. | PLUGGED VIAS TO BE PLATED AFTER PLUGGING TO PRESENT FLAT SURFACE TO DEVICE. | NO POTHOLES.
TOP: LAYER 1 - TOP
Ref Des/Assembly Top: COMPONENT SIDE | SOLDER SIDE
Board Geometry/Soldermask Top: SOLDERMASK TOP
Ref Des/Silkscreen Top: MOSIZ | SCLK | MISO | SEN | VADJ | 1.8V VADJ, CMOS | 2.5V VADJ, LVDS | SILKSCREEN TOP | DC069 | TEXAS INSTRUMENTS | TSW1418EVM REV A
LY2-GND: LAYER 2 (GND PLANE)
LY3-SIGNAL: LAYER 3 (PWR1)
LY4-GND: LAYER 4 (GND)
LY5-SIGNAL: LAYER 5 (PWR2)
LY6-GND: LAYER 6 (GND)
LY7-PWR: LAYER 7 (PWR3)
LYR8-GND: LAYER 8 GND
LYR9-PWR: LAYER 9 (PWR4)
DIMENSION: PASTEMASK TOP
BODY_CENTER: PASTEMASK BOTTOM
User.7: ASSEMBLY DRAWING,
User.14: FIGURE | SIZE | 8.0 | 10.0 | 38.0 | 40.0 | 55.0 | 62.0 | 67.0 | 106.0 | 120.0 | 125.0 | 140.0 | 39.0 | 41.0 | 50.0 | DRILL CHART: TOP to BOTTOM | ALL UNITS ARE IN MILS | PLATED | NON-PLATED | QTY | 876 | 235 | 8 | 20 | 2 | 4 | 16 | 1
User.17: R78 | C118 | R77 | C7 | C6 | C12 | C14 | C10 | FB2 | R5 | C2 | FB1 | C1 | C9 | C5 | C11 | C4 | C17 | C67 | C63 | C54 | C27 | C32 | C59 | C66 | C34 | C61 | C80 | C65 | C56 | R98 | C89 | C71 | R44 | C28 | C39 | C49 | C38 | C74 | C62 | C90 | R46 | R99 | C81 | C68 | C72 | C75 | C79 | C42 | C78 | C58 | C60 | C50 | C40 | C44 | C52 | C48 | C41 | C47 | C8 | C31 | C35 | C73 | C55 | C64 | C43 | C33 | C29 | R43 | C77 | C37 | C69 | R45 | C82 | C76 | C83 | C36 | C53 | C51 | C70 | C45 | C57 | R94 | R93 | R95
